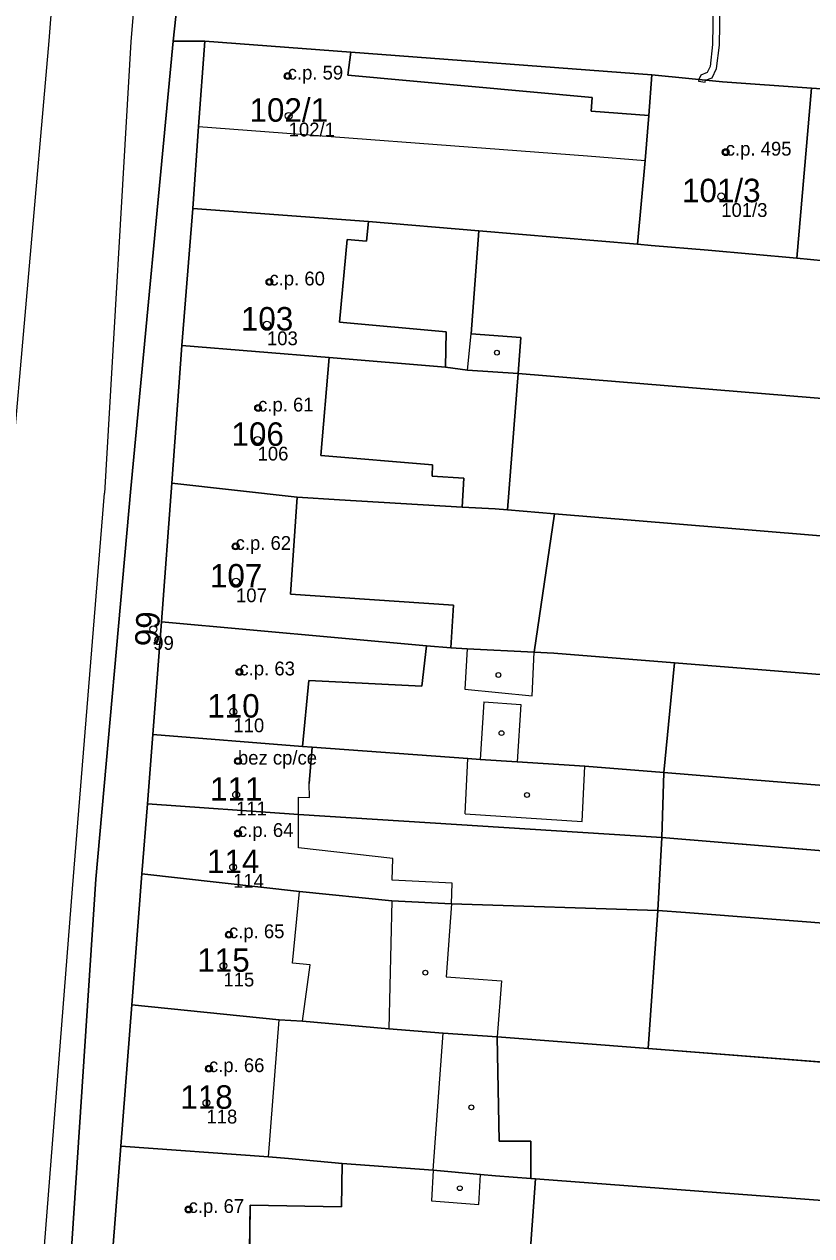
# Model space of a CAD drawing. Extents: x -603967 to -594699, y -1179315 to -1165625.
# Drawn here: x -597440.7 to -597383.7, y -1172751.9 to -1172664.1 of the extents above; entities that cross this region are included whole.
import ezdxf

# ---------------------------------------------------------------- set-up
doc = ezdxf.new("R2010")
doc.units = 0
for name, color, linetype in [('Definiční body', 7, 'Continuous'), ('Hranice parcel', 7, 'Continuous'), ('Parcelní čísla', 7, 'Continuous'), ('Polygon budovy', 7, 'Continuous'), ('Polygon parcely', 7, 'Continuous'), ('Vnitřní kresba', 7, 'Continuous'), ('Věcná břemena k části', 7, 'Continuous'), ('Značky budov', 7, 'Continuous')]:
    doc.layers.add(name, color=color, linetype=linetype)

msp = doc.modelspace()

# ---------------------------------------------------------------- linework, layer by layer
at = {"layer": 'Definiční body'}
for centre in [(-597421.64, -1172667.86994), (-597421.57, -1172670.74994), (-597389.93, -1172673.37994), (-597390.26, -1172676.57994), (-597422.96, -1172682.77994), (-597423.14, -1172685.86994), (-597423.78, -1172691.90994), (-597423.82, -1172694.21994), (-597425.41, -1172701.92994), (-597425.38, -1172704.47994), (-597431.37, -1172707.92994), (-597425.13, -1172711.01994), (-597425.57, -1172713.89994), (-597425.24, -1172717.47994), (-597425.37, -1172719.91994), (-597425.24, -1172722.71994), (-597425.59, -1172725.15994), (-597425.89, -1172730.04994), (-597426.29, -1172732.30994), (-597427.34, -1172739.74994), (-597427.52, -1172742.22994), (-597428.81, -1172749.94994)]:
    msp.add_circle(centre, 0.25, dxfattribs=at)
at = {"layer": 'Hranice parcel'}
for p, q in [((-597429.03, -1172657.03), (-597429.92, -1172665.33)), ((-597429.92, -1172665.33), (-597427.64, -1172665.35)), ((-597383.73, -1172668.74), (-597384.78, -1172681.06)), ((-597383.73, -1172668.74), (-597381.86, -1172668.86)), ((-597429.3, -1172687.37), (-597428.51, -1172677.45)), ((-597408.35, -1172686.53), (-597407.81, -1172679.07)), ((-597396.33, -1172680.05), (-597407.81, -1172679.07)), ((-597396.33, -1172680.05), (-597395.33, -1172680.13)), ((-597395.33, -1172680.13), (-597391.21, -1172680.48)), ((-597391.21, -1172680.48), (-597384.78, -1172681.06)), ((-597384.78, -1172681.06), (-597382.8, -1172681.24)), ((-597430.02, -1172697.34), (-597429.3, -1172687.37)), ((-597429.3, -1172687.37), (-597418.65, -1172688.25)), ((-597408.63, -1172689.17), (-597404.96, -1172689.4)), ((-597404.96, -1172689.4), (-597405.72, -1172699.28)), ((-597404.96, -1172689.4), (-597350.07, -1172693.93)), ((-597430.77, -1172707.4), (-597430.02, -1172697.34)), ((-597405.72, -1172699.28), (-597406.63, -1172699.22)), ((-597405.72, -1172699.28), (-597402.33, -1172699.56)), ((-597403.79, -1172709.59), (-597402.33, -1172699.56)), ((-597402.33, -1172699.56), (-597344.83, -1172704.33)), ((-597431.4, -1172715.56), (-597430.77, -1172707.4)), ((-597393.65, -1172710.36), (-597394.41, -1172718.3)), ((-597393.65, -1172710.36), (-597346.67, -1172714.12)), ((-597431.79, -1172720.58), (-597431.4, -1172715.56)), ((-597394.55, -1172723), (-597394.41, -1172718.3)), ((-597432.19, -1172725.63), (-597431.79, -1172720.58)), ((-597394.55, -1172723), (-597394.84, -1172728.3)), ((-597394.55, -1172723), (-597349.11, -1172726.77)), ((-597432.92, -1172735.13), (-597432.19, -1172725.63)), ((-597414.11, -1172727.6), (-597409.78, -1172727.81)), ((-597409.78, -1172727.81), (-597394.84, -1172728.3)), ((-597395.55, -1172738.3), (-597394.84, -1172728.3)), ((-597433.72, -1172745.36), (-597432.92, -1172735.13)), ((-597406.48, -1172737.44), (-597395.55, -1172738.3)), ((-597395.55, -1172738.3), (-597360.86, -1172740.99)), ((-597434.49, -1172755.32), (-597433.72, -1172745.36)), ((-597404.4, -1172757.46), (-597403.7, -1172747.72)), ((-597404.03, -1172747.7), (-597403.7, -1172747.72))]:
    msp.add_line(p, q, dxfattribs=at)
for points in [[(-597429.92, -1172665.33), (-597433, -1172697.73), (-597435.52, -1172726.03), (-597437.51, -1172756.08), (-597436.99, -1172763.55), (-597434.83, -1172767.52), (-597433.83, -1172770.44), (-597431.15, -1172771.68), (-597427, -1172773.05), (-597420.11, -1172775.61), (-597200.82, -1172818.32)], [(-597428.51, -1172677.45), (-597428.1, -1172671.53), (-597427.64, -1172665.35)], [(-597427.64, -1172665.35), (-597417.07, -1172666.15), (-597395.29, -1172667.78)], [(-597395.29, -1172667.78), (-597395.49, -1172670.73), (-597395.76, -1172673.98), (-597396.33, -1172680.05)], [(-597395.29, -1172667.78), (-597390.17, -1172668.29), (-597383.73, -1172668.74)], [(-597407.81, -1172679.07), (-597415.78, -1172678.39), (-597428.51, -1172677.45)], [(-597404.96, -1172689.4), (-597404.77, -1172686.81), (-597408.35, -1172686.53)], [(-597418.65, -1172688.25), (-597410.22, -1172688.96), (-597408.63, -1172689.17)], [(-597417.9, -1172698.56), (-597420.96, -1172698.37), (-597430.02, -1172697.34)], [(-597406.63, -1172699.22), (-597409.02, -1172699.08), (-597417.9, -1172698.56)], [(-597430.77, -1172707.4), (-597411.59, -1172709.13), (-597409.84, -1172709.28), (-597408.66, -1172709.34), (-597403.79, -1172709.59)], [(-597403.79, -1172709.59), (-597402.37, -1172709.66), (-597393.65, -1172710.36)], [(-597431.4, -1172715.56), (-597420.58, -1172716.41), (-597419.88, -1172716.46), (-597408.59, -1172717.29), (-597407.71, -1172717.35), (-597405.04, -1172717.53), (-597400.12, -1172717.84), (-597394.41, -1172718.3)], [(-597394.41, -1172718.3), (-597386.49, -1172718.95), (-597348.2, -1172721.99)], [(-597431.79, -1172720.58), (-597420.85, -1172721.34), (-597394.55, -1172723)], [(-597432.19, -1172725.63), (-597420.79, -1172726.93), (-597414.11, -1172727.6)], [(-597394.84, -1172728.3), (-597392.84, -1172728.43), (-597350.05, -1172731.76)], [(-597432.92, -1172735.13), (-597422.26, -1172736.22), (-597420.56, -1172736.32), (-597414.31, -1172736.87), (-597410.39, -1172737.17), (-597406.48, -1172737.44)], [(-597406.48, -1172737.44), (-597406.33, -1172745), (-597404.03, -1172745), (-597404.03, -1172747.7)], [(-597433.72, -1172745.36), (-597423.04, -1172746.14), (-597421.57, -1172746.26)], [(-597421.57, -1172746.26), (-597417.69, -1172746.61), (-597411.12, -1172747.1), (-597407.69, -1172747.42)], [(-597407.69, -1172747.42), (-597406.59, -1172747.5), (-597404.03, -1172747.7)], [(-597403.7, -1172747.72), (-597378.79, -1172749.6), (-597360.55, -1172750.94)]]:
    msp.add_lwpolyline(points, dxfattribs=at)
at = {"layer": 'Polygon budovy'}
for points in [[(-597427.64, -1172665.35), (-597428.1, -1172671.53), (-597399.93, -1172673.64), (-597395.76, -1172673.98), (-597395.49, -1172670.73), (-597399.68, -1172670.4), (-597399.6, -1172669.41), (-597417.28, -1172667.81), (-597417.07, -1172666.15)], [(-597395.76, -1172673.98), (-597396.33, -1172680.05), (-597395.33, -1172680.13), (-597391.21, -1172680.48), (-597384.78, -1172681.06), (-597383.73, -1172668.74), (-597390.17, -1172668.29), (-597395.29, -1172667.78), (-597395.49, -1172670.73)], [(-597429.3, -1172687.37), (-597418.65, -1172688.25), (-597410.22, -1172688.96), (-597410.18, -1172686.4), (-597417.89, -1172685.68), (-597417.34, -1172679.7), (-597415.94, -1172679.83), (-597415.78, -1172678.39), (-597428.51, -1172677.45)], [(-597418.65, -1172688.25), (-597429.3, -1172687.37), (-597430.02, -1172697.34), (-597420.96, -1172698.37), (-597417.9, -1172698.56), (-597409.02, -1172699.08), (-597408.89, -1172696.98), (-597411.19, -1172696.84), (-597411.15, -1172696.03), (-597419.24, -1172695.34)], [(-597430.77, -1172707.4), (-597411.59, -1172709.13), (-597409.84, -1172709.28), (-597409.64, -1172706.18), (-597421.43, -1172705.38), (-597420.96, -1172698.37), (-597430.02, -1172697.34)], [(-597431.4, -1172715.56), (-597420.58, -1172716.41), (-597420.11, -1172711.65), (-597411.94, -1172712.05), (-597411.59, -1172709.13), (-597430.77, -1172707.4)], [(-597431.4, -1172715.56), (-597431.79, -1172720.58), (-597420.85, -1172721.34), (-597420.85, -1172720.1), (-597420.05, -1172720.11), (-597420.08, -1172719.11), (-597419.88, -1172716.46), (-597420.58, -1172716.41)], [(-597431.79, -1172720.58), (-597432.19, -1172725.63), (-597420.79, -1172726.93), (-597414.11, -1172727.6), (-597409.78, -1172727.81), (-597409.74, -1172726.32), (-597414.07, -1172726.09), (-597414.03, -1172724.54), (-597420.85, -1172723.75), (-597420.85, -1172721.34)], [(-597432.19, -1172725.63), (-597432.92, -1172735.13), (-597422.26, -1172736.22), (-597420.56, -1172736.32), (-597420.02, -1172732.24), (-597421.29, -1172732.12), (-597420.79, -1172726.93)], [(-597432.92, -1172735.13), (-597433.72, -1172745.36), (-597423.04, -1172746.14), (-597422.26, -1172736.22)], [(-597434.49, -1172755.32), (-597424.45, -1172756.07), (-597424.35, -1172749.64), (-597417.75, -1172749.76), (-597417.69, -1172746.61), (-597421.57, -1172746.26), (-597423.04, -1172746.14), (-597433.72, -1172745.36)]]:
    msp.add_lwpolyline(points, close=True, dxfattribs=at)
at = {"layer": 'Polygon parcely'}
for points in [[(-597200.82, -1172818.32), (-597420.11, -1172775.61), (-597427, -1172773.05), (-597431.15, -1172771.68), (-597433.83, -1172770.44), (-597434.83, -1172767.52), (-597436.99, -1172763.55), (-597437.51, -1172756.08), (-597435.52, -1172726.03), (-597433, -1172697.73), (-597429.92, -1172665.33), (-597429.03, -1172657.03)], [(-597429.03, -1172657.03), (-597429.92, -1172665.33), (-597427.64, -1172665.35), (-597417.07, -1172666.15), (-597395.29, -1172667.78), (-597390.17, -1172668.29), (-597383.73, -1172668.74), (-597381.86, -1172668.86), (-597378.17, -1172669.14), (-597376.07, -1172669.29), (-597342.21, -1172671.62), (-597329.03, -1172672.79), (-597319.1, -1172673.54), (-597304.33, -1172674.66), (-597289.31, -1172675.79), (-597289.06, -1172677.65), (-597273.94, -1172676.94)], [(-597434.49, -1172755.32), (-597433.72, -1172745.36), (-597432.92, -1172735.13), (-597432.19, -1172725.63), (-597431.79, -1172720.58), (-597431.4, -1172715.56), (-597430.77, -1172707.4), (-597430.02, -1172697.34), (-597429.3, -1172687.37), (-597428.51, -1172677.45), (-597428.1, -1172671.53), (-597427.64, -1172665.35), (-597429.92, -1172665.33), (-597433, -1172697.73), (-597435.52, -1172726.03), (-597437.51, -1172756.08)]]:
    msp.add_lwpolyline(points, dxfattribs=at)
for points in [[(-597407.81, -1172679.07), (-597396.33, -1172680.05), (-597395.76, -1172673.98), (-597395.49, -1172670.73), (-597395.29, -1172667.78), (-597417.07, -1172666.15), (-597427.64, -1172665.35), (-597428.1, -1172671.53), (-597428.51, -1172677.45), (-597415.78, -1172678.39)], [(-597396.33, -1172680.05), (-597395.33, -1172680.13), (-597391.21, -1172680.48), (-597384.78, -1172681.06), (-597383.73, -1172668.74), (-597390.17, -1172668.29), (-597395.29, -1172667.78), (-597395.49, -1172670.73), (-597395.76, -1172673.98)], [(-597382.8, -1172681.24), (-597381.86, -1172668.86), (-597383.73, -1172668.74), (-597384.78, -1172681.06)], [(-597429.3, -1172687.37), (-597418.65, -1172688.25), (-597410.22, -1172688.96), (-597408.63, -1172689.17), (-597404.96, -1172689.4), (-597404.77, -1172686.81), (-597408.35, -1172686.53), (-597407.81, -1172679.07), (-597415.78, -1172678.39), (-597428.51, -1172677.45)], [(-597407.81, -1172679.07), (-597408.35, -1172686.53), (-597404.77, -1172686.81), (-597404.96, -1172689.4), (-597350.07, -1172693.93), (-597349.74, -1172689.9), (-597343.67, -1172690.39), (-597344, -1172694.43), (-597342.94, -1172694.46), (-597341.07, -1172684.74), (-597376.84, -1172681.72), (-597379.11, -1172681.53), (-597382.8, -1172681.24), (-597384.78, -1172681.06), (-597391.21, -1172680.48), (-597395.33, -1172680.13), (-597396.33, -1172680.05)], [(-597429.3, -1172687.37), (-597430.02, -1172697.34), (-597420.96, -1172698.37), (-597417.9, -1172698.56), (-597409.02, -1172699.08), (-597406.63, -1172699.22), (-597405.72, -1172699.28), (-597404.96, -1172689.4), (-597408.63, -1172689.17), (-597410.22, -1172688.96), (-597418.65, -1172688.25)], [(-597405.72, -1172699.28), (-597402.33, -1172699.56), (-597344.83, -1172704.33), (-597342.94, -1172694.46), (-597344, -1172694.43), (-597344.32, -1172698.36), (-597350.4, -1172697.96), (-597350.07, -1172693.93), (-597404.96, -1172689.4)], [(-597417.9, -1172698.56), (-597420.96, -1172698.37), (-597430.02, -1172697.34), (-597430.77, -1172707.4), (-597411.59, -1172709.13), (-597409.84, -1172709.28), (-597408.66, -1172709.34), (-597403.79, -1172709.59), (-597402.33, -1172699.56), (-597405.72, -1172699.28), (-597406.63, -1172699.22), (-597409.02, -1172699.08)], [(-597403.79, -1172709.59), (-597402.37, -1172709.66), (-597393.65, -1172710.36), (-597346.67, -1172714.12), (-597344.83, -1172704.33), (-597402.33, -1172699.56)], [(-597419.88, -1172716.46), (-597408.59, -1172717.29), (-597407.71, -1172717.35), (-597405.04, -1172717.53), (-597400.12, -1172717.84), (-597394.41, -1172718.3), (-597393.65, -1172710.36), (-597402.37, -1172709.66), (-597403.79, -1172709.59), (-597408.66, -1172709.34), (-597409.84, -1172709.28), (-597411.59, -1172709.13), (-597430.77, -1172707.4), (-597431.4, -1172715.56), (-597420.58, -1172716.41)], [(-597348.2, -1172721.99), (-597346.67, -1172714.12), (-597393.65, -1172710.36), (-597394.41, -1172718.3), (-597386.49, -1172718.95)], [(-597394.55, -1172723), (-597394.41, -1172718.3), (-597400.12, -1172717.84), (-597405.04, -1172717.53), (-597407.71, -1172717.35), (-597408.59, -1172717.29), (-597419.88, -1172716.46), (-597420.58, -1172716.41), (-597431.4, -1172715.56), (-597431.79, -1172720.58), (-597420.85, -1172721.34)], [(-597394.55, -1172723), (-597349.11, -1172726.77), (-597348.2, -1172721.99), (-597386.49, -1172718.95), (-597394.41, -1172718.3)], [(-597414.11, -1172727.6), (-597409.78, -1172727.81), (-597394.84, -1172728.3), (-597394.55, -1172723), (-597420.85, -1172721.34), (-597431.79, -1172720.58), (-597432.19, -1172725.63), (-597420.79, -1172726.93)], [(-597392.84, -1172728.43), (-597350.05, -1172731.76), (-597349.11, -1172726.77), (-597394.55, -1172723), (-597394.84, -1172728.3)], [(-597410.39, -1172737.17), (-597406.48, -1172737.44), (-597395.55, -1172738.3), (-597394.84, -1172728.3), (-597409.78, -1172727.81), (-597414.11, -1172727.6), (-597420.79, -1172726.93), (-597432.19, -1172725.63), (-597432.92, -1172735.13), (-597422.26, -1172736.22), (-597420.56, -1172736.32), (-597414.31, -1172736.87)], [(-597353.1, -1172741.63), (-597352.1, -1172741.71), (-597350.05, -1172731.76), (-597392.84, -1172728.43), (-597394.84, -1172728.3), (-597395.55, -1172738.3), (-597360.86, -1172740.99), (-597358.99, -1172741.13), (-597358.72, -1172737.49), (-597352.83, -1172737.97)], [(-597406.59, -1172747.5), (-597404.03, -1172747.7), (-597404.03, -1172745), (-597406.33, -1172745), (-597406.48, -1172737.44), (-597410.39, -1172737.17), (-597414.31, -1172736.87), (-597420.56, -1172736.32), (-597422.26, -1172736.22), (-597432.92, -1172735.13), (-597433.72, -1172745.36), (-597423.04, -1172746.14), (-597421.57, -1172746.26), (-597417.69, -1172746.61), (-597411.12, -1172747.1), (-597407.69, -1172747.42)], [(-597378.79, -1172749.6), (-597360.55, -1172750.94), (-597360.26, -1172747.65), (-597361.32, -1172747.53), (-597360.86, -1172740.99), (-597395.55, -1172738.3), (-597406.48, -1172737.44), (-597406.33, -1172745), (-597404.03, -1172745), (-597404.03, -1172747.7), (-597403.7, -1172747.72)], [(-597404.4, -1172757.46), (-597403.7, -1172747.72), (-597404.03, -1172747.7), (-597406.59, -1172747.5), (-597407.69, -1172747.42), (-597411.12, -1172747.1), (-597417.69, -1172746.61), (-597421.57, -1172746.26), (-597423.04, -1172746.14), (-597433.72, -1172745.36), (-597434.49, -1172755.32), (-597424.45, -1172756.07), (-597420.84, -1172756.37), (-597419.04, -1172756.44), (-597413.72, -1172756.79), (-597412.56, -1172756.87), (-597408.35, -1172757.15)], [(-597404.4, -1172757.46), (-597390.28, -1172758.59), (-597386.72, -1172758.87), (-597363.81, -1172760.54), (-597356.36, -1172761.08), (-597355.53, -1172761.26), (-597353.72, -1172751.44), (-597355.07, -1172751.34), (-597360.55, -1172750.94), (-597378.79, -1172749.6), (-597403.7, -1172747.72)]]:
    msp.add_lwpolyline(points, close=True, dxfattribs=at)
at = {"layer": 'Vnitřní kresba'}
for p, q in [((-597438.91, -1172665.32), (-597438.15, -1172655.85)), ((-597432.3, -1172656.61), (-597432.99, -1172665.38)), ((-597441.84, -1172699.01), (-597438.91, -1172665.32)), ((-597432.99, -1172665.38), (-597434.9, -1172698.08)), ((-597417.07, -1172666.15), (-597417.28, -1172667.81)), ((-597417.28, -1172667.81), (-597399.6, -1172669.41)), ((-597399.6, -1172669.41), (-597399.68, -1172670.4)), ((-597399.68, -1172670.4), (-597395.49, -1172670.73)), ((-597428.1, -1172671.53), (-597399.93, -1172673.64)), ((-597399.93, -1172673.64), (-597395.76, -1172673.98)), ((-597415.78, -1172678.39), (-597415.94, -1172679.83)), ((-597417.34, -1172679.7), (-597417.89, -1172685.68)), ((-597415.94, -1172679.83), (-597417.34, -1172679.7)), ((-597417.89, -1172685.68), (-597410.18, -1172686.4)), ((-597410.18, -1172686.4), (-597410.22, -1172688.96)), ((-597408.63, -1172689.17), (-597408.35, -1172686.53)), ((-597418.65, -1172688.25), (-597419.24, -1172695.34)), ((-597419.24, -1172695.34), (-597411.15, -1172696.03)), ((-597411.15, -1172696.03), (-597411.19, -1172696.84)), ((-597411.19, -1172696.84), (-597408.89, -1172696.98)), ((-597408.89, -1172696.98), (-597409.02, -1172699.08)), ((-597437.21, -1172726.73), (-597434.9, -1172698.08)), ((-597420.96, -1172698.37), (-597421.43, -1172705.38)), ((-597421.43, -1172705.38), (-597409.64, -1172706.18)), ((-597409.64, -1172706.18), (-597409.84, -1172709.28)), ((-597411.59, -1172709.13), (-597411.94, -1172712.05)), ((-597408.66, -1172709.34), (-597408.81, -1172712.26)), ((-597403.95, -1172712.74), (-597403.79, -1172709.59)), ((-597420.11, -1172711.65), (-597420.58, -1172716.41)), ((-597411.94, -1172712.05), (-597420.11, -1172711.65)), ((-597408.81, -1172712.26), (-597403.95, -1172712.74)), ((-597407.45, -1172713.19), (-597407.71, -1172717.35)), ((-597407.45, -1172713.19), (-597404.77, -1172713.37)), ((-597404.77, -1172713.37), (-597405.04, -1172717.53)), ((-597419.88, -1172716.46), (-597420.08, -1172719.11)), ((-597408.8, -1172721.3), (-597408.59, -1172717.29)), ((-597400.32, -1172721.85), (-597400.12, -1172717.84)), ((-597420.05, -1172720.11), (-597420.08, -1172719.11)), ((-597420.85, -1172720.1), (-597420.05, -1172720.11)), ((-597420.85, -1172721.34), (-597420.85, -1172720.1)), ((-597420.85, -1172723.75), (-597420.85, -1172721.34)), ((-597408.8, -1172721.3), (-597400.32, -1172721.85)), ((-597414.03, -1172724.54), (-597420.85, -1172723.75)), ((-597414.07, -1172726.09), (-597414.03, -1172724.54)), ((-597409.74, -1172726.32), (-597414.07, -1172726.09)), ((-597409.78, -1172727.81), (-597409.74, -1172726.32)), ((-597439.57, -1172756.74), (-597437.21, -1172726.73)), ((-597421.29, -1172732.12), (-597420.79, -1172726.93)), ((-597414.11, -1172727.6), (-597414.31, -1172736.87)), ((-597409.78, -1172727.81), (-597410.18, -1172733.09)), ((-597420.02, -1172732.24), (-597421.29, -1172732.12)), ((-597420.56, -1172736.32), (-597420.02, -1172732.24)), ((-597410.18, -1172733.09), (-597406.17, -1172733.39)), ((-597406.17, -1172733.39), (-597406.48, -1172737.44)), ((-597423.04, -1172746.14), (-597422.26, -1172736.22)), ((-597411.12, -1172747.1), (-597410.39, -1172737.17)), ((-597417.69, -1172746.61), (-597417.75, -1172749.76)), ((-597411.12, -1172747.1), (-597411.24, -1172749.32)), ((-597407.8, -1172749.59), (-597407.69, -1172747.42)), ((-597424.35, -1172749.64), (-597424.45, -1172756.07)), ((-597417.75, -1172749.76), (-597424.35, -1172749.64)), ((-597411.24, -1172749.32), (-597407.8, -1172749.59))]:
    msp.add_line(p, q, dxfattribs=at)
at = {"layer": 'Věcná břemena k části'}
for points in [[(-597400.43, -1172657.46), (-597400.07, -1172657.82), (-597399.64, -1172657.34), (-597394.88, -1172657.7), (-597391, -1172658.19), (-597390.76, -1172658.39), (-597390.89, -1172665.59), (-597391.07, -1172667.18), (-597391.28, -1172667.62), (-597391.73, -1172667.8), (-597391.89, -1172668.12), (-597391.39, -1172668.17), (-597390.92, -1172668), (-597390.59, -1172667.32), (-597390.39, -1172665.63), (-597390.26, -1172658.15), (-597390.8, -1172657.71), (-597394.82, -1172657.2), (-597399.88, -1172656.82)], [(-597391.89, -1172668.12), (-597391.9, -1172668.25), (-597391.41, -1172668.3), (-597391.39, -1172668.17)]]:
    msp.add_lwpolyline(points, close=True, dxfattribs=at)
at = {"layer": 'Značky budov'}
for centre in [(-597421.6468, -1172667.86916), (-597389.9368, -1172673.37916), (-597422.9668, -1172682.77916), (-597406.4968, -1172687.89916), (-597423.7868, -1172691.90916), (-597425.4168, -1172701.92916), (-597425.1368, -1172711.01916), (-597406.3868, -1172711.23916), (-597406.1668, -1172715.44916), (-597425.2468, -1172717.47916), (-597404.3168, -1172719.92916), (-597425.2468, -1172722.71916), (-597425.8968, -1172730.04916), (-597411.6768, -1172732.79916), (-597427.3468, -1172739.74916), (-597408.3468, -1172742.54916), (-597409.1768, -1172748.40916), (-597428.8168, -1172749.94916)]:
    msp.add_circle(centre, 0.175, dxfattribs=at)

# ---------------------------------------------------------------- texts
at = {"layer": 'Definiční body'}
for s, p in [('c.p. 59', (-597421.64, -1172668.12)), ('102/1', (-597421.57, -1172672.239)), ('c.p. 495', (-597389.93, -1172673.63)), ('101/3', (-597390.26, -1172678.069)), ('c.p. 60', (-597422.96, -1172683.03)), ('103', (-597423.14, -1172687.359)), ('c.p. 61', (-597423.78, -1172692.16)), ('106', (-597423.82, -1172695.709)), ('c.p. 62', (-597425.41, -1172702.18)), ('107', (-597425.38, -1172705.969)), ('99', (-597431.37, -1172709.419)), ('c.p. 63', (-597425.13, -1172711.27)), ('110', (-597425.57, -1172715.389)), ('bez cp/ce', (-597425.24, -1172717.73)), ('111', (-597425.37, -1172721.409)), ('c.p. 64', (-597425.24, -1172722.97)), ('114', (-597425.59, -1172726.649)), ('c.p. 65', (-597425.89, -1172730.3)), ('115', (-597426.29, -1172733.799)), ('c.p. 66', (-597427.34, -1172740)), ('118', (-597427.52, -1172743.719)), ('c.p. 67', (-597428.81, -1172750.2))]:
    msp.add_text(s, height=0.999996, dxfattribs=at).set_placement(p)
at = {"layer": 'Parcelní čísla'}
for s, p in [('102/1', (-597424.406, -1172671.175)), ('101/3', (-597393.096, -1172677.005)), ('103', (-597425.03, -1172686.295)), ('106', (-597425.71, -1172694.645)), ('107', (-597427.27, -1172704.905)), ('110', (-597427.46, -1172714.325)), ('111', (-597427.26, -1172720.345)), ('114', (-597427.48, -1172725.585)), ('115', (-597428.18, -1172732.735)), ('118', (-597429.41, -1172742.655))]:
    msp.add_text(s, height=1.699998, dxfattribs=at).set_placement(p)
msp.add_text('99', height=1.699998, rotation=87, dxfattribs=at).set_placement((-597431.011, -1172709.211))

doc.saveas('drawing.dxf')
